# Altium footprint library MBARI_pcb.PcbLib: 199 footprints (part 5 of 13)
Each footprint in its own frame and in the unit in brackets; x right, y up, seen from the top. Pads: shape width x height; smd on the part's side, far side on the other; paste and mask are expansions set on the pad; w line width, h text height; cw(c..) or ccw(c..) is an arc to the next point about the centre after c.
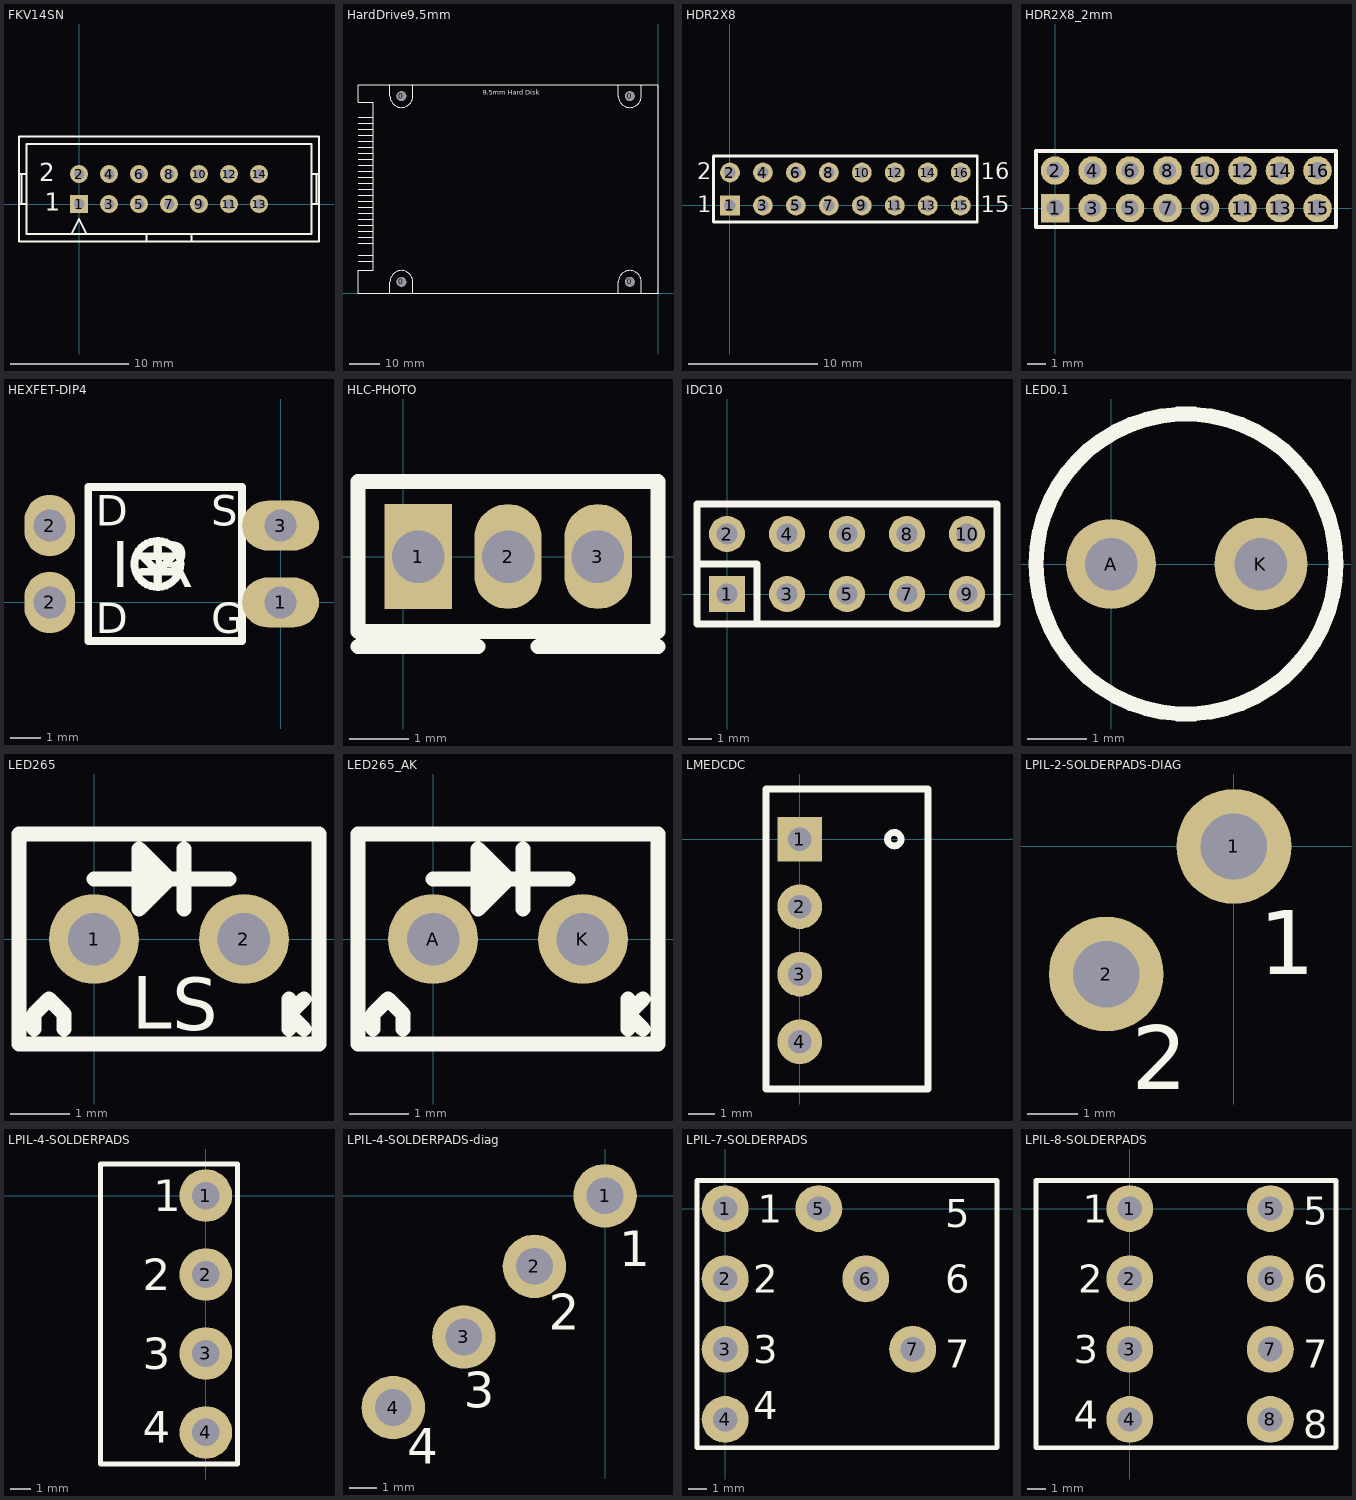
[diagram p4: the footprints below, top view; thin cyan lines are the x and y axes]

## FKV14SN [mil]
pads (14):
  rect 60x60 hole 35: 1(0,0)
  round 60 hole 35: 2(0,100) 3(100,0) 4(100,100) 5(200,0) 6(200,100) 7(300,0) 8(300,100) 9(400,0) 10(400,100) 11(500,0) 12(500,100) 13(600,0) 14(600,100)
TopOverlay:
  lines w8: -200,0 -175,0 ; -200,100 -175,100 ; -191.67,0 -191.67,100 ; -25,-100 0,-50 25,-100 ; 225,-125 225,-100 ; 375,-125 375,-100 ; 775,0 800,0 ; 775,100 800,100 ; 791.67,0 791.67,100 ; 225,-100 375,-100 ; 225,-100 -175,-100 -175,200 775,200 775,-100 375,-100 ; -200,-125 800,-125 800,225 -200,225 -200,-125
  text "2" at -132,76 h60
  text "1" at -115,-23 h60

## HardDrive9.5mm [mil] "Laptop Hard Drive"
height 375
pads (4):
  round 130 hole 125: 0(-3370,150) 0(-3370,2590) 0(-370,150) 0(-370,2590)
TopOverlay:
  lines w7: -3940,1365.12 -3740,1365.12
  lines w10: -3940,420.24 -3740,420.24 ; -3940,498.98 -3740,498.98 ; -3940,656.46 -3740,656.46 ; -3940,735.2 -3740,735.2 ; -3940,813.94 -3740,813.94 ; -3940,892.68 -3740,892.68 ; -3940,971.42 -3740,971.42 ; -3940,1050.16 -3740,1050.16 ; -3940,1128.9 -3740,1128.9 ; -3940,1207.64 -3740,1207.64 ; -3940,1286.38 -3740,1286.38 ; -3940,1443.86 -3740,1443.86 ; -3940,1522.6 -3740,1522.6 ; -3940,1601.34 -3740,1601.34 ; -3940,1680.08 -3740,1680.08 ; -3940,1758.82 -3740,1758.82 ; -3940,1837.56 -3740,1837.56 ; -3940,1916.3 -3740,1916.3 ; -3940,1995.04 -3740,1995.04 ; -3940,2073.78 -3740,2073.78 ; -3940,2152.52 -3740,2152.52 ; -3940,2231.26 -3740,2231.26 ; -3940,2310 -3740,2310 ; -3520,0 -3520,150 cw(c-3370,150) -3220,150 -3220,0 ; -3520,2740 -3520,2590 ccw(c-3370,2590) -3220,2590 -3220,2740 ; -520,0 -520,150 cw(c-370,150) -220,150 -220,0 ; -520,2740 -520,2590 ccw(c-370,2590) -220,2590 -220,2740 ; -3940,0 -3940,300 -3740,300 -3740,2510 -3940,2510 -3940,2740 0,2740 0,0 -3940,0
  text "9.5mm Hard Disk" at -2300,2610 h60

## HDR2X8 [mil]
pads (16):
  rect 60x60 hole 35: 1(0,-0.39)
  round 60 hole 35: 2(0,99.61) 3(100,-0.39) 4(100,99.61) 5(200,-0.39) 6(200,99.61) 7(300,-0.39) 8(300,99.61) 9(400,-0.39) 10(400,99.61) 11(500,-0.39) 12(500,99.61) 13(600,-0.39) 14(600,99.61) 15(700,-0.39) 16(700,99.61)
TopOverlay:
  lines w8: -50,-50.39 -50,149.61 750,149.61 750,-50.39 -50,-50.39
  text "2" at -100,79.61 h50
  text "1" at -100,-20.39 h50
  text "15" at 760,-20.39 h50
  text "16" at 760,79.61 h50

## HDR2X8_2mm [mil]
pads (16):
  rect 60x60 hole 35: 1(0,0)
  round 60 hole 35: 2(0,78.74) 3(78.74,0) 4(78.74,78.74) 5(157.48,0) 6(157.48,78.74) 7(236.22,0) 8(236.22,78.74) 9(314.96,0) 10(314.96,78.74) 11(393.7,0) 12(393.7,78.74) 13(472.44,0) 14(472.44,78.74) 15(551.18,0) 16(551.18,78.74)
TopOverlay:
  lines w8: -40,-40 -40,120 590,120 590,-40 -40,-40

## HEXFET-DIP4 [mil]
pads (4):
  oval 100x65 hole 42: 1(0,0) 3(0,100)
  oval 66x80 hole 42: 2(-300,0) 2(-300,100)
TopOverlay:
  circle w10: c-160,50 r30
  lines w10: -180,40 -140,40 ; -160,20 -160,40 ; -160,80 -160,60 ; -160,40 -180,60 -160,60 ; -160,40 -140,60 -160,60 ; -250,-50 -50,-50 -50,150 -250,150 -250,-50
  text "I R" at -220,20 h60
  text "S" at -90,100 h40
  text "G" at -90,-40 h40
  text "D" at -240,100 h40
  text "D" at -240,-40 h40

## HLC-PHOTO [mil]
pads (3):
  rect 45x70 hole 35: 1(10,0)
  oval 45x70 hole 35: 2(70,0) 3(130,0)
TopOverlay:
  lines w10: -30,-60 50,-60 ; 90,-60 170,-60 ; -30,-50 170,-50 170,50 -30,50 -30,-50

## IDC10 [mil]
pads (10):
  rect 60x60 hole 35: 1(0,0)
  round 60 hole 35: 2(0,100) 3(100,0) 4(100,100) 5(200,0) 6(200,100) 7(300,0) 8(300,100) 9(400,0) 10(400,100)
TopOverlay:
  lines w12: -50,50 50,50 50,-50 ; -50,-50 -50,150 450,150 450,-50 -50,-50

## LED0.1 [mil]
pads (2):
  round 60 hole 35: A(0,0)
  round 62 hole 35: K(100,0)
TopOverlay:
  circle w10: c50,0 r100

## LED265 [mil]
pads (2):
  round 60 hole 35: 1(0,0) 2(100,0)
TopOverlay:
  lines w10: -40,-60 -40,-50 -30,-40 -20,-50 -20,-60 ; 0,40 30,40 ; 36.22,26.22 36.22,53.78 ; 60,20 60,40 60,60 ; 90,40 30,40 ; 130,-40 130,-60 130,-50 ; 140,-60 130,-50 ; 30,40 30,60 ; 30,60 50,40 30,20 30,60 ; 130,-50 140,-40 130,-50 ; -50,-70 150,-70 150,70 -50,70 -50,-70
  text "S" at 52,-61 h35
  text "L" at 25,-60 h35

## LED265_AK [mil]
pads (2):
  round 60 hole 35: A(0,0) K(100,0)
TopOverlay:
  lines w10: -40,-60 -40,-50 -30,-40 -20,-50 -20,-60 ; 0,40 30,40 ; 36.22,26.22 36.22,53.78 ; 60,20 60,40 60,60 ; 90,40 30,40 ; 130,-40 130,-60 130,-50 ; 140,-60 130,-50 ; 30,40 30,60 ; 30,60 50,40 30,20 30,60 ; 130,-50 140,-40 130,-50 ; -50,-70 150,-70 150,70 -50,70 -50,-70

## LMEDCDC [mil] "C&D Tech DCDC LME"
height 39
pads (4):
  rect 66x66 hole 35: 1(0,0)
  round 66 hole 35: 2(0,-100) 3(0,-200) 4(0,-300)
TopOverlay:
  circle w10: c140,0 r10
  lines w10: -50,-370 -50,74.25 190,74.25 190,-370 -50,-370

## LPIL-2-SOLDERPADS-DIAG [mil]
pads (2):
  round 90 hole 52: 1(0,0) 2(-100,-100)
TopOverlay:
  text "2" at -80,-190 h50
  text "1" at 20,-100 h50

## LPIL-4-SOLDERPADS [mil]
pads (4):
  round 100 hole 52: 1(0,0) 2(0,-150) 3(0,-300) 4(0,-450)
TopOverlay:
  lines w10: -200,-510 -200,60 60,60 60,-510 -200,-510
  text "4" at -120,-470 h60
  text "3" at -120,-330 h60
  text "2" at -120,-180 h60
  text "1" at -100,-30 h60

## LPIL-4-SOLDERPADS-diag [mil]
pads (4):
  round 90 hole 52: 1(0,0) 2(-100,-100) 3(-200,-200) 4(-300,-300)
TopOverlay:
  text "1" at 20,-100 h50
  text "2" at -80,-190 h50
  text "3" at -200,-300 h50
  text "4" at -280,-380 h50

## LPIL-7-SOLDERPADS [mil]
pads (7):
  round 100 hole 52: 1(0,0) 2(0,-150) 3(0,-300) 4(0,-450) 5(200,0) 6(300,-150) 7(400,-300)
TopOverlay:
  lines w10: -60,-510 580,-510 580,60 -60,60 -60,-510
  text "7" at 470,-340 h60
  text "6" at 470,-180 h60
  text "5" at 470,-40 h60
  text "4" at 60,-450 h60
  text "3" at 60,-330 h60
  text "2" at 60,-180 h60
  text "1" at 70,-30 h60

## LPIL-8-SOLDERPADS [mil]
pads (8):
  round 100 hole 52: 1(0,0) 2(0,-150) 3(0,-300) 4(0,-450) 5(300,0) 6(300,-150) 7(300,-300) 8(300,-450)
TopOverlay:
  lines w10: -200,-510 -200,60 440,60 440,-510 -200,-510
  text "1" at -100,-30 h60
  text "2" at -110,-180 h60
  text "3" at -120,-330 h60
  text "4" at -120,-470 h60
  text "5" at 370,-35 h60
  text "6" at 370,-180 h60
  text "7" at 370,-340 h60
  text "8" at 370,-490 h60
